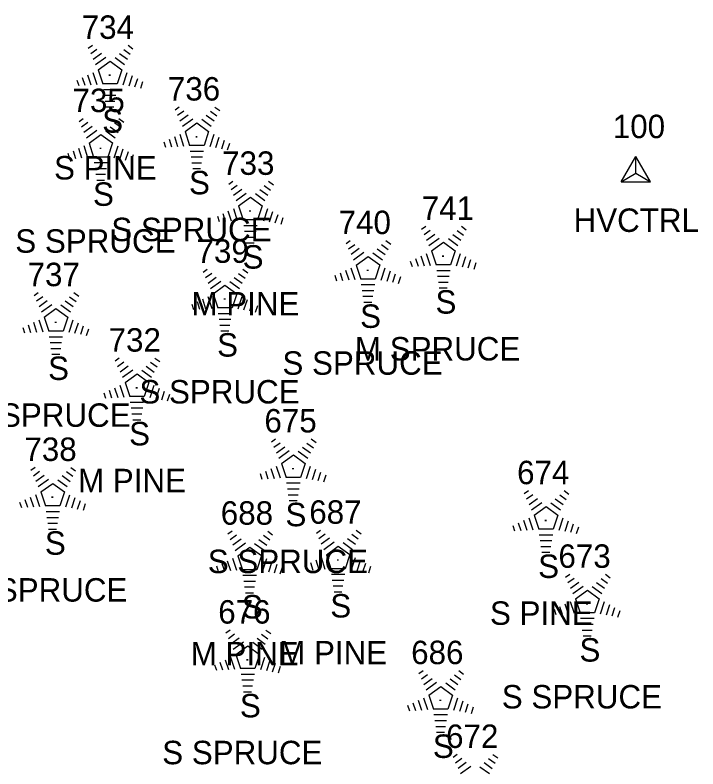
# Model space of a CAD drawing. Extents: x 1545627 to 1546562, y 571176 to 576667.
# Drawn here: x 1546262.6 to 1546320.9, y 572214.6 to 572278.9 of the extents above; entities that cross this region are included whole.
import ezdxf

# ---------------------------------------------------------------- set-up
doc = ezdxf.new("R2010")
doc.units = 0
for name, color, linetype in [('C_A', 7, 'Continuous'), ('C_I', 7, 'Continuous'), ('CPSM', 7, 'Continuous'), ('L_A', 7, 'Continuous'), ('L_C', 7, 'Continuous'), ('L_I', 7, 'Continuous'), ('LTC', 7, 'Continuous')]:
    doc.layers.add(name, color=color, linetype=linetype)

msp = doc.modelspace()

# ---------------------------------------------------------------- linework, layer by layer
at = {"layer": 'CPSM'}
for p, q in [((1546314.373, 572264.687), (1546315.623, 572266.852)), ((1546316.873, 572264.687), (1546315.623, 572266.852)), ((1546315.623, 572265.408), (1546315.623, 572266.852)), ((1546314.373, 572264.687), (1546315.623, 572265.408)), ((1546315.623, 572265.408), (1546315.623, 572265.408)), ((1546315.623, 572265.408), (1546316.873, 572264.687)), ((1546314.373, 572264.687), (1546316.873, 572264.687))]:
    msp.add_line(p, q, dxfattribs=at)
at = {"layer": 'LTC'}
for p, q in [((1546268.895, 572276.088), (1546269.249, 572276.345)), ((1546269.104, 572275.623), (1546269.634, 572276.007)), ((1546271.922, 572275.98), (1546272.472, 572275.581)), ((1546272.293, 572276.328), (1546272.712, 572276.024)), ((1546269.314, 572275.157), (1546270.018, 572275.668)), ((1546269.524, 572274.691), (1546270.402, 572275.329)), ((1546271.18, 572275.283), (1546271.989, 572274.695)), ((1546271.551, 572275.632), (1546272.23, 572275.138)), ((1546269.748, 572274.236), (1546270.76, 572274.97)), ((1546270.76, 572274.97), (1546271.757, 572274.245)), ((1546269.294, 572274.017), (1546269.624, 572272.998)), ((1546269.748, 572274.236), (1546270.135, 572273.043)), ((1546271.757, 572274.245), (1546271.366, 572273.043)), ((1546272.194, 572273.975), (1546271.857, 572272.935)), ((1546267.927, 572273.367), (1546268.079, 572272.899)), ((1546268.383, 572273.584), (1546268.594, 572272.932)), ((1546268.838, 572273.8), (1546269.109, 572272.965)), ((1546272.639, 572273.724), (1546272.352, 572272.84)), ((1546273.084, 572273.474), (1546272.847, 572272.745)), ((1546273.528, 572273.224), (1546273.341, 572272.65)), ((1546271.366, 572273.043), (1546270.135, 572273.043)), ((1546271.327, 572272.543), (1546270.183, 572272.543)), ((1546271.244, 572272.043), (1546270.255, 572272.043)), ((1546271.16, 572271.543), (1546270.328, 572271.543)), ((1546271.076, 572271.043), (1546270.401, 572271.043)), ((1546276.304, 572270.825), (1546276.658, 572271.082)), ((1546276.513, 572270.359), (1546277.043, 572270.743)), ((1546279.331, 572270.717), (1546279.88, 572270.318)), ((1546279.702, 572271.065), (1546280.121, 572270.761)), ((1546268.108, 572269.841), (1546268.462, 572270.098)), ((1546271.506, 572270.081), (1546271.925, 572269.777)), ((1546276.723, 572269.893), (1546277.427, 572270.405)), ((1546276.933, 572269.428), (1546277.811, 572270.066)), ((1546278.589, 572270.02), (1546279.398, 572269.431)), ((1546278.96, 572270.368), (1546279.639, 572269.875)), ((1546268.317, 572269.376), (1546268.847, 572269.76)), ((1546268.527, 572268.91), (1546269.231, 572269.421)), ((1546270.764, 572269.385), (1546271.443, 572268.891)), ((1546271.135, 572269.733), (1546271.684, 572269.334)), ((1546277.157, 572268.973), (1546278.169, 572269.707)), ((1546278.169, 572269.707), (1546279.166, 572268.982)), ((1546268.737, 572268.444), (1546269.615, 572269.082)), ((1546268.961, 572267.989), (1546269.973, 572268.723)), ((1546269.973, 572268.723), (1546270.97, 572267.998)), ((1546270.393, 572269.036), (1546271.202, 572268.448)), ((1546276.703, 572268.753), (1546277.033, 572267.734)), ((1546277.157, 572268.973), (1546277.544, 572267.779)), ((1546279.166, 572268.982), (1546278.775, 572267.779)), ((1546279.603, 572268.711), (1546279.265, 572267.672)), ((1546275.336, 572268.104), (1546275.488, 572267.636)), ((1546275.792, 572268.321), (1546276.003, 572267.669)), ((1546276.247, 572268.537), (1546276.518, 572267.702)), ((1546280.048, 572268.461), (1546279.76, 572267.576)), ((1546280.493, 572268.211), (1546280.255, 572267.481)), ((1546268.051, 572267.553), (1546268.322, 572266.718)), ((1546268.507, 572267.77), (1546268.837, 572266.751)), ((1546268.961, 572267.989), (1546269.348, 572266.796)), ((1546270.97, 572267.998), (1546270.579, 572266.796)), ((1546271.407, 572267.728), (1546271.069, 572266.688)), ((1546271.852, 572267.477), (1546271.564, 572266.593)), ((1546278.775, 572267.779), (1546277.544, 572267.779)), ((1546280.937, 572267.961), (1546280.75, 572267.386)), ((1546267.14, 572267.12), (1546267.292, 572266.652)), ((1546267.596, 572267.337), (1546267.807, 572266.685)), ((1546270.579, 572266.796), (1546269.348, 572266.796)), ((1546272.297, 572267.227), (1546272.059, 572266.498)), ((1546272.741, 572266.977), (1546272.554, 572266.403)), ((1546278.736, 572267.279), (1546277.592, 572267.279)), ((1546278.653, 572266.779), (1546277.664, 572266.779)), ((1546270.54, 572266.296), (1546269.396, 572266.296)), ((1546278.569, 572266.279), (1546277.737, 572266.279)), ((1546270.457, 572265.796), (1546269.468, 572265.796)), ((1546278.485, 572265.779), (1546277.81, 572265.779)), ((1546270.373, 572265.296), (1546269.541, 572265.296)), ((1546270.289, 572264.796), (1546269.614, 572264.796)), ((1546280.878, 572264.485), (1546281.233, 572264.742)), ((1546281.088, 572264.019), (1546281.617, 572264.403)), ((1546283.905, 572264.377), (1546284.455, 572263.978)), ((1546284.276, 572264.725), (1546284.696, 572264.421)), ((1546281.297, 572263.553), (1546282.001, 572264.065)), ((1546281.507, 572263.088), (1546282.385, 572263.726)), ((1546283.163, 572263.68), (1546283.973, 572263.091)), ((1546283.534, 572264.028), (1546284.214, 572263.535)), ((1546281.731, 572262.633), (1546282.743, 572263.367)), ((1546282.743, 572263.367), (1546283.74, 572262.642)), ((1546281.277, 572262.413), (1546281.608, 572261.394)), ((1546281.731, 572262.633), (1546282.119, 572261.439)), ((1546283.74, 572262.642), (1546283.349, 572261.439)), ((1546284.178, 572262.371), (1546283.84, 572261.332)), ((1546279.911, 572261.764), (1546280.063, 572261.296)), ((1546280.366, 572261.981), (1546280.578, 572261.329)), ((1546280.821, 572262.197), (1546281.093, 572261.362)), ((1546284.622, 572262.121), (1546284.335, 572261.236)), ((1546285.067, 572261.871), (1546284.83, 572261.141)), ((1546285.511, 572261.621), (1546285.324, 572261.046)), ((1546283.349, 572261.439), (1546282.119, 572261.439)), ((1546283.311, 572260.939), (1546282.166, 572260.939)), ((1546283.227, 572260.439), (1546282.239, 572260.439)), ((1546297.343, 572260.644), (1546297.697, 572260.902)), ((1546297.552, 572260.179), (1546298.081, 572260.563)), ((1546300.37, 572260.537), (1546300.919, 572260.137)), ((1546300.741, 572260.885), (1546301.16, 572260.58)), ((1546283.143, 572259.939), (1546282.311, 572259.939)), ((1546290.906, 572259.428), (1546291.261, 572259.686)), ((1546294.304, 572259.668), (1546294.724, 572259.364)), ((1546297.762, 572259.713), (1546298.466, 572260.224)), ((1546297.971, 572259.247), (1546298.85, 572259.885)), ((1546299.628, 572259.84), (1546300.437, 572259.251)), ((1546299.999, 572260.188), (1546300.678, 572259.694)), ((1546283.059, 572259.439), (1546282.384, 572259.439)), ((1546291.116, 572258.963), (1546291.645, 572259.347)), ((1546291.325, 572258.497), (1546292.029, 572259.008)), ((1546293.933, 572259.32), (1546294.483, 572258.921)), ((1546298.196, 572258.792), (1546299.208, 572259.527)), ((1546299.208, 572259.527), (1546300.205, 572258.802)), ((1546291.535, 572258.031), (1546292.413, 572258.669)), ((1546293.191, 572258.623), (1546294.001, 572258.035)), ((1546293.562, 572258.972), (1546294.241, 572258.478)), ((1546297.741, 572258.573), (1546298.072, 572257.554)), ((1546298.196, 572258.792), (1546298.583, 572257.599)), ((1546300.205, 572258.802), (1546299.814, 572257.599)), ((1546300.642, 572258.531), (1546300.304, 572257.492)), ((1546291.759, 572257.576), (1546292.771, 572258.311)), ((1546292.771, 572258.311), (1546293.768, 572257.586)), ((1546296.375, 572257.924), (1546296.527, 572257.456)), ((1546296.831, 572258.14), (1546297.042, 572257.489)), ((1546297.286, 572258.357), (1546297.557, 572257.522)), ((1546301.087, 572258.281), (1546300.799, 572257.396)), ((1546301.531, 572258.031), (1546301.294, 572257.301)), ((1546301.976, 572257.78), (1546301.789, 572257.206)), ((1546278.7, 572256.977), (1546279.055, 572257.235)), ((1546282.099, 572257.218), (1546282.518, 572256.913)), ((1546290.849, 572257.141), (1546291.121, 572256.305)), ((1546291.305, 572257.357), (1546291.636, 572256.338)), ((1546291.759, 572257.576), (1546292.146, 572256.383)), ((1546293.768, 572257.586), (1546293.377, 572256.383)), ((1546294.206, 572257.315), (1546293.868, 572256.275)), ((1546299.814, 572257.599), (1546298.583, 572257.599)), ((1546299.775, 572257.099), (1546298.631, 572257.099)), ((1546278.91, 572256.512), (1546279.439, 572256.896)), ((1546279.119, 572256.046), (1546279.823, 572256.557)), ((1546281.357, 572256.521), (1546282.036, 572256.027)), ((1546281.727, 572256.869), (1546282.277, 572256.47)), ((1546289.939, 572256.707), (1546290.091, 572256.239)), ((1546290.394, 572256.924), (1546290.606, 572256.272)), ((1546294.65, 572257.064), (1546294.363, 572256.18)), ((1546295.095, 572256.814), (1546294.858, 572256.085)), ((1546295.539, 572256.564), (1546295.352, 572255.99)), ((1546299.691, 572256.599), (1546298.703, 572256.599)), ((1546279.329, 572255.58), (1546280.207, 572256.218)), ((1546279.554, 572255.125), (1546280.565, 572255.86)), ((1546280.565, 572255.86), (1546281.562, 572255.135)), ((1546280.985, 572256.173), (1546281.795, 572255.584)), ((1546293.377, 572256.383), (1546292.146, 572256.383)), ((1546293.339, 572255.883), (1546292.194, 572255.883)), ((1546299.608, 572256.099), (1546298.776, 572256.099)), ((1546264.276, 572254.985), (1546264.631, 572255.242)), ((1546267.675, 572255.225), (1546268.094, 572254.921)), ((1546293.255, 572255.383), (1546292.266, 572255.383)), ((1546299.524, 572255.599), (1546298.849, 572255.599)), ((1546264.486, 572254.519), (1546265.015, 572254.904)), ((1546264.696, 572254.054), (1546265.399, 572254.565)), ((1546266.933, 572254.529), (1546267.612, 572254.035)), ((1546267.304, 572254.877), (1546267.853, 572254.478)), ((1546278.644, 572254.69), (1546278.915, 572253.854)), ((1546279.099, 572254.906), (1546279.43, 572253.887)), ((1546279.554, 572255.125), (1546279.941, 572253.932)), ((1546281.562, 572255.135), (1546281.171, 572253.932)), ((1546282, 572254.864), (1546281.662, 572253.824)), ((1546282.444, 572254.613), (1546282.157, 572253.729)), ((1546293.171, 572254.883), (1546292.339, 572254.883)), ((1546264.905, 572253.588), (1546265.784, 572254.226)), ((1546265.13, 572253.133), (1546266.141, 572253.867)), ((1546266.141, 572253.867), (1546267.139, 572253.142)), ((1546266.561, 572254.18), (1546267.371, 572253.591)), ((1546277.733, 572254.256), (1546277.885, 572253.788)), ((1546278.188, 572254.473), (1546278.4, 572253.821)), ((1546281.171, 572253.932), (1546279.941, 572253.932)), ((1546282.889, 572254.363), (1546282.652, 572253.634)), ((1546283.333, 572254.113), (1546283.147, 572253.539)), ((1546293.087, 572254.383), (1546292.412, 572254.383)), ((1546281.133, 572253.432), (1546279.988, 572253.432)), ((1546264.22, 572252.697), (1546264.491, 572251.862)), ((1546264.675, 572252.914), (1546265.006, 572251.894)), ((1546265.13, 572253.133), (1546265.517, 572251.939)), ((1546267.139, 572253.142), (1546266.747, 572251.939)), ((1546267.576, 572252.871), (1546267.238, 572251.832)), ((1546268.021, 572252.621), (1546267.733, 572251.736)), ((1546281.049, 572252.932), (1546280.061, 572252.932)), ((1546263.309, 572252.264), (1546263.461, 572251.796)), ((1546263.764, 572252.481), (1546263.976, 572251.829)), ((1546266.747, 572251.939), (1546265.517, 572251.939)), ((1546268.465, 572252.371), (1546268.228, 572251.641)), ((1546268.909, 572252.121), (1546268.723, 572251.546)), ((1546280.965, 572252.432), (1546280.134, 572252.432)), ((1546280.882, 572251.932), (1546280.207, 572251.932)), ((1546266.709, 572251.439), (1546265.564, 572251.439)), ((1546266.625, 572250.939), (1546265.637, 572250.939)), ((1546266.541, 572250.439), (1546265.71, 572250.439)), ((1546266.458, 572249.939), (1546265.783, 572249.939)), ((1546271.191, 572249.402), (1546271.546, 572249.66)), ((1546274.589, 572249.643), (1546275.008, 572249.338)), ((1546271.401, 572248.937), (1546271.93, 572249.321)), ((1546271.61, 572248.471), (1546272.314, 572248.982)), ((1546273.847, 572248.946), (1546274.526, 572248.452)), ((1546274.218, 572249.294), (1546274.768, 572248.895)), ((1546271.82, 572248.005), (1546272.698, 572248.643)), ((1546272.044, 572247.55), (1546273.056, 572248.285)), ((1546273.056, 572248.285), (1546274.053, 572247.56)), ((1546273.476, 572248.598), (1546274.286, 572248.009)), ((1546272.044, 572247.55), (1546272.431, 572246.357)), ((1546274.053, 572247.56), (1546273.662, 572246.357)), ((1546270.679, 572246.898), (1546270.891, 572246.246)), ((1546271.134, 572247.115), (1546271.406, 572246.279)), ((1546271.59, 572247.331), (1546271.921, 572246.312)), ((1546274.491, 572247.289), (1546274.153, 572246.249)), ((1546274.935, 572247.039), (1546274.648, 572246.154)), ((1546275.38, 572246.789), (1546275.143, 572246.059)), ((1546270.223, 572246.681), (1546270.376, 572246.214)), ((1546273.662, 572246.357), (1546272.431, 572246.357)), ((1546275.824, 572246.538), (1546275.637, 572245.964)), ((1546273.623, 572245.857), (1546272.479, 572245.857)), ((1546273.54, 572245.357), (1546272.551, 572245.357)), ((1546273.456, 572244.857), (1546272.624, 572244.857)), ((1546273.372, 572244.357), (1546272.697, 572244.357)), ((1546284.535, 572242.503), (1546284.889, 572242.76)), ((1546284.744, 572242.037), (1546285.274, 572242.422)), ((1546287.562, 572242.395), (1546288.112, 572241.996)), ((1546287.933, 572242.743), (1546288.352, 572242.439)), ((1546284.954, 572241.572), (1546285.658, 572242.083)), ((1546285.164, 572241.106), (1546286.042, 572241.744)), ((1546286.82, 572241.698), (1546287.629, 572241.109)), ((1546287.191, 572242.047), (1546287.87, 572241.553)), ((1546285.388, 572240.651), (1546286.4, 572241.385)), ((1546286.4, 572241.385), (1546287.397, 572240.66)), ((1546284.934, 572240.432), (1546285.264, 572239.412)), ((1546285.388, 572240.651), (1546285.775, 572239.457)), ((1546287.397, 572240.66), (1546287.006, 572239.457)), ((1546287.834, 572240.389), (1546287.497, 572239.35)), ((1546264.002, 572240.072), (1546264.356, 572240.329)), ((1546264.211, 572239.606), (1546264.741, 572239.991)), ((1546267.029, 572239.964), (1546267.579, 572239.565)), ((1546267.4, 572240.312), (1546267.819, 572240.008)), ((1546283.567, 572239.782), (1546283.72, 572239.314)), ((1546284.023, 572239.999), (1546284.234, 572239.347)), ((1546284.478, 572240.215), (1546284.749, 572239.38)), ((1546288.279, 572240.139), (1546287.992, 572239.255)), ((1546288.724, 572239.889), (1546288.487, 572239.16)), ((1546264.421, 572239.141), (1546265.125, 572239.652)), ((1546264.631, 572238.675), (1546265.509, 572239.313)), ((1546266.287, 572239.267), (1546267.096, 572238.678)), ((1546266.658, 572239.616), (1546267.337, 572239.122)), ((1546287.006, 572239.457), (1546285.775, 572239.457)), ((1546289.168, 572239.639), (1546288.981, 572239.065)), ((1546264.855, 572238.22), (1546265.867, 572238.954)), ((1546265.867, 572238.954), (1546266.864, 572238.229)), ((1546286.967, 572238.957), (1546285.823, 572238.957)), ((1546286.884, 572238.457), (1546285.895, 572238.457)), ((1546263.945, 572237.784), (1546264.216, 572236.949)), ((1546264.401, 572238.001), (1546264.731, 572236.981)), ((1546264.855, 572238.22), (1546265.242, 572237.026)), ((1546266.864, 572238.229), (1546266.473, 572237.026)), ((1546267.301, 572237.958), (1546266.964, 572236.919)), ((1546286.8, 572237.957), (1546285.968, 572237.957)), ((1546306.1, 572238.091), (1546306.454, 572238.348)), ((1546306.309, 572237.625), (1546306.839, 572238.009)), ((1546309.127, 572237.983), (1546309.677, 572237.584)), ((1546309.498, 572238.331), (1546309.917, 572238.026)), ((1546263.034, 572237.351), (1546263.186, 572236.883)), ((1546263.49, 572237.568), (1546263.701, 572236.916)), ((1546267.746, 572237.708), (1546267.459, 572236.823)), ((1546268.191, 572237.458), (1546267.954, 572236.728)), ((1546268.635, 572237.208), (1546268.448, 572236.633)), ((1546286.716, 572237.457), (1546286.041, 572237.457)), ((1546306.519, 572237.159), (1546307.223, 572237.671)), ((1546306.729, 572236.694), (1546307.607, 572237.331)), ((1546308.385, 572237.286), (1546309.194, 572236.697)), ((1546308.756, 572237.634), (1546309.435, 572237.141)), ((1546266.473, 572237.026), (1546265.242, 572237.026)), ((1546266.434, 572236.526), (1546265.29, 572236.526)), ((1546306.953, 572236.239), (1546307.965, 572236.973)), ((1546307.965, 572236.973), (1546308.962, 572236.248)), ((1546266.351, 572236.026), (1546265.362, 572236.026)), ((1546306.499, 572236.019), (1546306.829, 572235)), ((1546306.953, 572236.239), (1546307.34, 572235.045)), ((1546308.962, 572236.248), (1546308.571, 572235.045)), ((1546309.399, 572235.977), (1546309.062, 572234.938)), ((1546266.267, 572235.526), (1546265.435, 572235.526)), ((1546305.132, 572235.37), (1546305.284, 572234.902)), ((1546305.588, 572235.586), (1546305.799, 572234.935)), ((1546306.043, 572235.803), (1546306.314, 572234.968)), ((1546309.844, 572235.727), (1546309.557, 572234.842)), ((1546310.289, 572235.477), (1546310.052, 572234.747)), ((1546310.733, 572235.226), (1546310.546, 572234.652)), ((1546266.183, 572235.026), (1546265.508, 572235.026)), ((1546280.81, 572234.634), (1546281.164, 572234.891)), ((1546284.208, 572234.874), (1546284.627, 572234.569)), ((1546288.362, 572234.716), (1546288.717, 572234.973)), ((1546288.572, 572234.25), (1546289.101, 572234.634)), ((1546291.389, 572234.608), (1546291.939, 572234.209)), ((1546291.761, 572234.956), (1546292.18, 572234.651)), ((1546308.571, 572235.045), (1546307.34, 572235.045)), ((1546281.019, 572234.168), (1546281.548, 572234.552)), ((1546281.229, 572233.702), (1546281.933, 572234.214)), ((1546283.466, 572234.177), (1546284.145, 572233.684)), ((1546283.837, 572234.526), (1546284.386, 572234.126)), ((1546288.781, 572233.784), (1546289.485, 572234.296)), ((1546288.991, 572233.319), (1546289.869, 572233.956)), ((1546291.019, 572234.259), (1546291.698, 572233.766)), ((1546308.532, 572234.545), (1546307.388, 572234.545)), ((1546308.449, 572234.045), (1546307.46, 572234.045)), ((1546281.438, 572233.236), (1546282.317, 572233.874)), ((1546281.663, 572232.781), (1546282.675, 572233.516)), ((1546282.675, 572233.516), (1546283.672, 572232.791)), ((1546283.095, 572233.829), (1546283.904, 572233.24)), ((1546289.216, 572232.864), (1546290.227, 572233.598)), ((1546290.227, 572233.598), (1546291.224, 572232.873)), ((1546290.647, 572233.911), (1546291.457, 572233.322)), ((1546308.365, 572233.545), (1546307.533, 572233.545)), ((1546281.663, 572232.781), (1546282.05, 572231.588)), ((1546283.672, 572232.791), (1546283.28, 572231.588)), ((1546288.761, 572232.644), (1546289.092, 572231.625)), ((1546289.216, 572232.864), (1546289.603, 572231.67)), ((1546291.224, 572232.873), (1546290.833, 572231.67)), ((1546308.281, 572233.045), (1546307.606, 572233.045)), ((1546280.298, 572232.129), (1546280.509, 572231.478)), ((1546280.753, 572232.346), (1546281.024, 572231.511)), ((1546281.208, 572232.562), (1546281.539, 572231.543)), ((1546284.109, 572232.52), (1546283.771, 572231.481)), ((1546284.554, 572232.27), (1546284.266, 572231.385)), ((1546284.998, 572232.02), (1546284.761, 572231.29)), ((1546287.395, 572231.995), (1546287.547, 572231.527)), ((1546287.85, 572232.211), (1546288.062, 572231.56)), ((1546288.306, 572232.428), (1546288.577, 572231.593)), ((1546291.662, 572232.602), (1546291.324, 572231.563)), ((1546292.106, 572232.352), (1546291.819, 572231.467)), ((1546292.551, 572232.102), (1546292.314, 572231.372)), ((1546279.842, 572231.913), (1546279.994, 572231.445)), ((1546283.28, 572231.588), (1546282.05, 572231.588)), ((1546285.443, 572231.769), (1546285.256, 572231.195)), ((1546290.833, 572231.67), (1546289.603, 572231.67)), ((1546292.995, 572231.851), (1546292.809, 572231.277)), ((1546283.242, 572231.088), (1546282.098, 572231.088)), ((1546290.795, 572231.17), (1546289.65, 572231.17)), ((1546309.627, 572230.954), (1546309.982, 572231.212)), ((1546309.837, 572230.489), (1546310.366, 572230.873)), ((1546312.655, 572230.846), (1546313.204, 572230.447)), ((1546313.026, 572231.195), (1546313.445, 572230.89)), ((1546283.158, 572230.588), (1546282.17, 572230.588)), ((1546283.075, 572230.088), (1546282.243, 572230.088)), ((1546290.711, 572230.67), (1546289.723, 572230.67)), ((1546290.627, 572230.17), (1546289.796, 572230.17)), ((1546310.047, 572230.023), (1546310.75, 572230.534)), ((1546310.256, 572229.557), (1546311.135, 572230.195)), ((1546311.912, 572230.15), (1546312.722, 572229.561)), ((1546312.284, 572230.498), (1546312.963, 572230.004)), ((1546282.991, 572229.588), (1546282.316, 572229.588)), ((1546290.544, 572229.67), (1546289.869, 572229.67)), ((1546310.481, 572229.102), (1546311.492, 572229.837)), ((1546311.492, 572229.837), (1546312.49, 572229.112)), ((1546310.026, 572228.883), (1546310.357, 572227.864)), ((1546310.481, 572229.102), (1546310.868, 572227.909)), ((1546312.49, 572229.112), (1546312.098, 572227.909)), ((1546312.927, 572228.841), (1546312.589, 572227.801)), ((1546308.66, 572228.233), (1546308.812, 572227.765)), ((1546309.115, 572228.45), (1546309.327, 572227.798)), ((1546309.571, 572228.667), (1546309.842, 572227.831)), ((1546313.372, 572228.59), (1546313.084, 572227.706)), ((1546313.816, 572228.34), (1546313.579, 572227.611)), ((1546312.098, 572227.909), (1546310.868, 572227.909)), ((1546314.26, 572228.09), (1546314.074, 572227.516)), ((1546312.06, 572227.409), (1546310.915, 572227.409)), ((1546311.976, 572226.909), (1546310.988, 572226.909)), ((1546280.647, 572226.195), (1546281.001, 572226.452)), ((1546284.045, 572226.435), (1546284.464, 572226.131)), ((1546311.892, 572226.409), (1546311.061, 572226.409)), ((1546280.856, 572225.729), (1546281.385, 572226.113)), ((1546281.066, 572225.263), (1546281.769, 572225.775)), ((1546283.303, 572225.738), (1546283.982, 572225.245)), ((1546283.674, 572226.087), (1546284.223, 572225.688)), ((1546311.809, 572225.909), (1546311.134, 572225.909)), ((1546281.275, 572224.798), (1546282.154, 572225.436)), ((1546281.5, 572224.343), (1546282.512, 572225.077)), ((1546282.512, 572225.077), (1546283.509, 572224.352)), ((1546282.932, 572225.39), (1546283.741, 572224.801)), ((1546281.5, 572224.343), (1546281.887, 572223.149)), ((1546283.509, 572224.352), (1546283.117, 572223.149)), ((1546280.135, 572223.691), (1546280.346, 572223.039)), ((1546280.59, 572223.907), (1546280.861, 572223.072)), ((1546281.045, 572224.123), (1546281.376, 572223.104)), ((1546283.946, 572224.081), (1546283.608, 572223.042)), ((1546284.391, 572223.831), (1546284.103, 572222.946)), ((1546279.679, 572223.474), (1546279.831, 572223.006)), ((1546283.117, 572223.149), (1546281.887, 572223.149)), ((1546284.835, 572223.581), (1546284.598, 572222.851)), ((1546285.279, 572223.331), (1546285.093, 572222.756)), ((1546297.114, 572222.735), (1546297.469, 572222.992)), ((1546283.079, 572222.649), (1546281.934, 572222.649)), ((1546297.324, 572222.269), (1546297.853, 572222.654)), ((1546300.141, 572222.627), (1546300.691, 572222.228)), ((1546300.513, 572222.975), (1546300.932, 572222.671)), ((1546282.995, 572222.149), (1546282.007, 572222.149)), ((1546297.533, 572221.804), (1546298.237, 572222.315)), ((1546297.743, 572221.338), (1546298.621, 572221.976)), ((1546299.399, 572221.93), (1546300.209, 572221.341)), ((1546299.77, 572222.279), (1546300.45, 572221.785)), ((1546282.912, 572221.649), (1546282.08, 572221.649)), ((1546282.828, 572221.149), (1546282.153, 572221.149)), ((1546297.968, 572220.883), (1546298.979, 572221.617)), ((1546298.979, 572221.617), (1546299.976, 572220.892)), ((1546297.058, 572220.447), (1546297.329, 572219.612)), ((1546297.513, 572220.664), (1546297.844, 572219.644)), ((1546297.968, 572220.883), (1546298.355, 572219.689)), ((1546299.976, 572220.892), (1546299.585, 572219.689)), ((1546300.414, 572220.621), (1546300.076, 572219.582)), ((1546296.147, 572220.014), (1546296.299, 572219.546)), ((1546296.602, 572220.231), (1546296.814, 572219.579)), ((1546300.858, 572220.371), (1546300.571, 572219.486)), ((1546301.303, 572220.121), (1546301.066, 572219.391)), ((1546301.747, 572219.871), (1546301.56, 572219.296)), ((1546299.585, 572219.689), (1546298.355, 572219.689)), ((1546299.547, 572219.189), (1546298.402, 572219.189)), ((1546299.463, 572218.689), (1546298.475, 572218.689)), ((1546299.379, 572218.189), (1546298.548, 572218.189)), ((1546299.295, 572217.689), (1546298.62, 572217.689)), ((1546300.038, 572215.584), (1546300.392, 572215.841)), ((1546300.247, 572215.119), (1546300.776, 572215.503)), ((1546303.065, 572215.476), (1546303.614, 572215.077)), ((1546303.436, 572215.824), (1546303.855, 572215.52)), ((1546300.457, 572214.653), (1546301.161, 572215.164)), ((1546300.666, 572214.187), (1546301.545, 572214.825)), ((1546302.323, 572214.779), (1546303.132, 572214.191)), ((1546302.694, 572215.128), (1546303.373, 572214.634))]:
    msp.add_line(p, q, dxfattribs=at)

# ---------------------------------------------------------------- texts
at = {"layer": 'C_A'}
msp.add_text('HVCTRL', height=2, dxfattribs=at).set_placement((1546310.316, 572260.408))
at = {"layer": 'C_I'}
msp.add_text('100', height=2, dxfattribs=at).set_placement((1546313.663, 572268.408))
at = {"layer": 'L_A'}
for p in [(1546270.086, 572268.88), (1546277.494, 572263.617), (1546269.298, 572262.633), (1546282.069, 572257.277), (1546298.533, 572253.436), (1546292.097, 572252.22), (1546279.891, 572249.769), (1546265.467, 572247.777), (1546272.382, 572242.194), (1546285.726, 572235.295), (1546265.193, 572232.864), (1546307.291, 572230.882), (1546282, 572227.425), (1546289.553, 572227.507), (1546310.818, 572223.746), (1546281.837, 572218.987), (1546298.305, 572215.527)]:
    msp.add_text('S', height=2, dxfattribs=at).set_placement(p)
at = {"layer": 'L_C'}
for s, p in [('S PINE', (1546265.975, 572264.88)), ('S SPRUCE', (1546270.865, 572259.617)), ('S SPRUCE', (1546262.669, 572258.633)), ('M PINE', (1546277.707, 572253.277)), ('M SPRUCE', (1546291.652, 572249.436)), ('S SPRUCE', (1546285.467, 572248.22)), ('S SPRUCE', (1546273.261, 572245.769)), ('S SPRUCE', (1546258.837, 572243.777)), ('M PINE', (1546268.019, 572238.194)), ('S SPRUCE', (1546279.096, 572231.295)), ('S SPRUCE', (1546258.563, 572228.864)), ('S PINE', (1546303.18, 572226.882)), ('M PINE', (1546277.638, 572223.425)), ('M PINE', (1546285.191, 572223.507)), ('S SPRUCE', (1546304.188, 572219.746)), ('S SPRUCE', (1546275.207, 572214.987))]:
    msp.add_text(s, height=2, dxfattribs=at).set_placement(p)
at = {"layer": 'L_I'}
for s, p in [('734', (1546268.337, 572276.88)), ('736', (1546275.691, 572271.617)), ('735', (1546267.55, 572270.633)), ('733', (1546280.321, 572265.277)), ('741', (1546297.352, 572261.436)), ('740', (1546290.262, 572260.22)), ('739', (1546278.135, 572257.769)), ('737', (1546263.719, 572255.777)), ('732', (1546270.634, 572250.194)), ('675', (1546283.93, 572243.295)), ('738', (1546263.445, 572240.864)), ('674', (1546305.495, 572238.882)), ('688', (1546280.205, 572235.425)), ('687', (1546287.758, 572235.507)), ('673', (1546309.023, 572231.746)), ('676', (1546279.987, 572226.987)), ('686', (1546296.454, 572223.527)), ('672', (1546299.433, 572216.376))]:
    msp.add_text(s, height=2, dxfattribs=at).set_placement(p)
at = {"layer": 'LTC'}
for p in [(1546270.642, 572273.984), (1546278.051, 572268.721), (1546269.855, 572267.737), (1546282.626, 572262.381), (1546299.09, 572258.54), (1546292.654, 572257.324), (1546280.448, 572254.873), (1546266.024, 572252.881), (1546272.938, 572247.298), (1546286.282, 572240.399), (1546265.749, 572237.968), (1546307.847, 572235.986), (1546282.557, 572232.529), (1546290.11, 572232.611), (1546311.375, 572228.85), (1546282.394, 572224.091), (1546298.862, 572220.631)]:
    msp.add_text('.', height=1.037, rotation=270, dxfattribs=at).set_placement(p)

doc.saveas('drawing.dxf')
